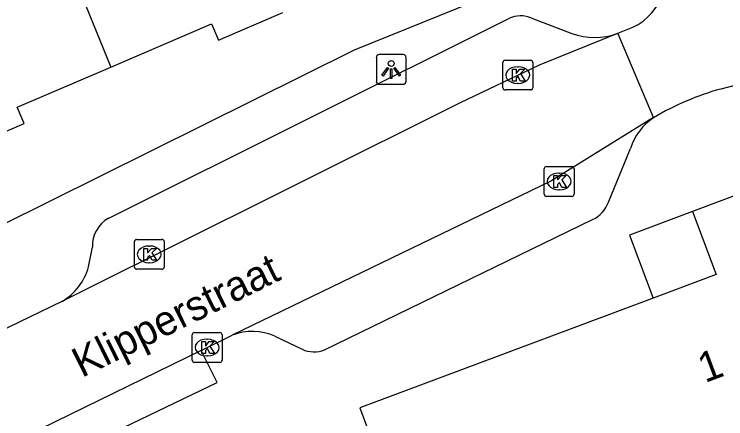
# Model space of a CAD drawing. Extents: x 159377 to 159983, y 382996 to 383595.
# Drawn here: x 159565.6 to 159589.46, y 383433.49 to 383447.05 of the extents above; entities that cross this region are included whole.
import ezdxf

# ---------------------------------------------------------------- set-up
doc = ezdxf.new("R2010")
doc.units = 0
for name, color, linetype in [('IMGEO_Kolk', 7, 'Continuous'), ('IMGEO_Lichtpunt', 7, 'Continuous'), ('IMGEO_Openbare_ruimte_label', 7, 'Continuous'), ('IMGEO_Pand', 7, 'Continuous'), ('IMGEO_Pand_nummerreeks', 7, 'Continuous'), ('IMGEO_Rijbaan_lokaal_gesloten', 7, 'Continuous'), ('IMGEO_Rijbaan_lokaal_open', 7, 'Continuous'), ('IMGEO_Voetpad_open', 7, 'Continuous')]:
    doc.layers.add(name, color=color, linetype=linetype)

msp = doc.modelspace()

# ---------------------------------------------------------------- linework, layer by layer
at = {"layer": 'IMGEO_Kolk'}
for p, q in [((159582.061, 383445.512), (159582.913, 383445.512)), ((159581.986, 383444.586), (159581.986, 383445.438)), ((159582.474, 383445.292), (159582.499, 383445.292)), ((159582.987, 383445.438), (159582.987, 383444.586)), ((159582.497, 383444.732), (159582.472, 383444.732)), ((159582.913, 383444.512), (159582.061, 383444.512)), ((159583.374, 383441.02), (159583.374, 383441.872)), ((159583.449, 383441.946), (159584.301, 383441.946)), ((159584.375, 383441.872), (159584.375, 383441.02)), ((159583.862, 383441.726), (159583.887, 383441.726)), ((159583.885, 383441.166), (159583.86, 383441.166)), ((159584.301, 383440.946), (159583.449, 383440.946)), ((159569.706, 383439.501), (159570.558, 383439.501)), ((159569.631, 383438.575), (159569.631, 383439.427)), ((159570.119, 383439.281), (159570.144, 383439.281)), ((159570.632, 383439.427), (159570.632, 383438.575)), ((159570.142, 383438.721), (159570.117, 383438.721)), ((159570.558, 383438.501), (159569.706, 383438.501)), ((159571.646, 383436.377), (159572.498, 383436.377)), ((159571.571, 383435.451), (159571.571, 383436.303)), ((159572.059, 383436.157), (159572.084, 383436.157)), ((159572.572, 383436.303), (159572.572, 383435.451)), ((159572.082, 383435.597), (159572.057, 383435.597)), ((159572.498, 383435.377), (159571.646, 383435.377))]:
    msp.add_line(p, q, dxfattribs=at)
for points in [[(159582.061, 383445.512), (159582.913, 383445.512)], [(159581.986, 383444.586), (159581.986, 383445.438)], [(159582.307, 383445.212), (159582.43, 383445.212), (159582.43, 383445.061), (159582.56, 383445.212), (159582.724, 383445.212), (159582.578, 383445.061), (159582.731, 383444.812), (159582.579, 383444.812), (159582.494, 383444.976), (159582.43, 383444.909), (159582.43, 383444.812), (159582.307, 383444.812), (159582.307, 383445.212)], [(159582.987, 383445.438), (159582.987, 383444.586)], [(159582.913, 383444.512), (159582.061, 383444.512)], [(159583.374, 383441.02), (159583.374, 383441.872)], [(159583.449, 383441.946), (159584.301, 383441.946)], [(159584.375, 383441.872), (159584.375, 383441.02)], [(159583.695, 383441.646), (159583.818, 383441.646), (159583.818, 383441.495), (159583.948, 383441.646), (159584.112, 383441.646), (159583.966, 383441.495), (159584.119, 383441.246), (159583.967, 383441.246), (159583.882, 383441.41), (159583.818, 383441.343), (159583.818, 383441.246), (159583.695, 383441.246), (159583.695, 383441.646)], [(159584.301, 383440.946), (159583.449, 383440.946)], [(159569.706, 383439.501), (159570.558, 383439.501)], [(159569.631, 383438.575), (159569.631, 383439.427)], [(159570.632, 383439.427), (159570.632, 383438.575)], [(159569.952, 383439.201), (159570.075, 383439.201), (159570.075, 383439.05), (159570.205, 383439.201), (159570.369, 383439.201), (159570.223, 383439.05), (159570.376, 383438.801), (159570.224, 383438.801), (159570.139, 383438.965), (159570.075, 383438.898), (159570.075, 383438.801), (159569.952, 383438.801), (159569.952, 383439.201)], [(159570.558, 383438.501), (159569.706, 383438.501)], [(159571.646, 383436.377), (159572.498, 383436.377)], [(159571.571, 383435.451), (159571.571, 383436.303)], [(159572.572, 383436.303), (159572.572, 383435.451)], [(159571.892, 383436.077), (159572.015, 383436.077), (159572.015, 383435.926), (159572.145, 383436.077), (159572.309, 383436.077), (159572.163, 383435.926), (159572.316, 383435.677), (159572.164, 383435.677), (159572.079, 383435.841), (159572.015, 383435.774), (159572.015, 383435.677), (159571.892, 383435.677), (159571.892, 383436.077)], [(159572.498, 383435.377), (159571.646, 383435.377)]]:
    msp.add_lwpolyline(points, dxfattribs=at)
for centre, start, end in [((159582.063, 383445.436), 91.552, 178.448), ((159582.063, 383445.436), 91.552, 178.448), ((159582.911, 383445.436), 1.552, 88.448), ((159582.911, 383445.436), 1.552, 88.448), ((159582.063, 383444.588), 181.552, 268.448), ((159582.063, 383444.588), 181.552, 268.448), ((159582.911, 383444.588), 271.552, 358.448), ((159582.911, 383444.588), 271.552, 358.448), ((159583.451, 383441.87), 91.552, 178.448), ((159583.451, 383441.87), 91.552, 178.448), ((159584.299, 383441.87), 1.552, 88.448), ((159584.299, 383441.87), 1.552, 88.448), ((159583.451, 383441.022), 181.552, 268.448), ((159583.451, 383441.022), 181.552, 268.448), ((159584.299, 383441.022), 271.552, 358.448), ((159584.299, 383441.022), 271.552, 358.448), ((159569.708, 383439.425), 91.552, 178.448), ((159569.708, 383439.425), 91.552, 178.448), ((159570.556, 383439.425), 1.552, 88.448), ((159570.556, 383439.425), 1.552, 88.448), ((159569.708, 383438.577), 181.552, 268.448), ((159569.708, 383438.577), 181.552, 268.448), ((159570.556, 383438.577), 271.552, 358.448), ((159570.556, 383438.577), 271.552, 358.448), ((159571.648, 383436.301), 91.552, 178.448), ((159571.648, 383436.301), 91.552, 178.448), ((159572.496, 383436.301), 1.552, 88.448), ((159572.496, 383436.301), 1.552, 88.448), ((159571.648, 383435.453), 181.552, 268.448), ((159571.648, 383435.453), 181.552, 268.448), ((159572.496, 383435.453), 271.552, 358.448), ((159572.496, 383435.453), 271.552, 358.448)]:
    msp.add_arc(centre, 0.0765, start, end, dxfattribs=at)
for centre, major_axis, ratio, start_param, end_param in [((159582.473, 383445.012), (-0.387, 0.002), 0.722429, 4.712389, 7.853982), ((159582.498, 383445.012), (-0.39, 0.002), 0.717154, 1.570796, 4.712389), ((159583.861, 383441.446), (-0.387, 0.002), 0.722429, 4.712389, 7.853982), ((159583.886, 383441.446), (-0.39, 0.002), 0.717154, 1.570796, 4.712389), ((159570.118, 383439.001), (-0.387, 0.002), 0.722429, 4.712389, 7.853982), ((159570.143, 383439.001), (-0.39, 0.002), 0.717154, 1.570796, 4.712389), ((159572.058, 383435.877), (-0.387, 0.002), 0.722429, 4.712389, 7.853982), ((159572.083, 383435.877), (-0.39, 0.002), 0.717154, 1.570796, 4.712389)]:
    msp.add_ellipse(centre, major_axis=major_axis, ratio=ratio, start_param=start_param, end_param=end_param, dxfattribs=at)
at = {"layer": 'IMGEO_Lichtpunt'}
for p, q in [((159578.647, 383445.699), (159577.839, 383445.699)), ((159578.647, 383445.699), (159577.839, 383445.699)), ((159577.745, 383445.604), (159577.745, 383444.797)), ((159577.745, 383445.604), (159577.745, 383444.797)), ((159578.741, 383444.797), (159578.741, 383445.604)), ((159578.741, 383444.797), (159578.741, 383445.604)), ((159577.839, 383444.703), (159578.647, 383444.703)), ((159577.839, 383444.703), (159578.647, 383444.703))]:
    msp.add_line(p, q, dxfattribs=at)
for points in [[(159578.119, 383445.268), (159578.158, 383445.24), (159577.97, 383444.978), (159577.932, 383445.005), (159578.119, 383445.268)], [(159578.221, 383445.22), (159578.268, 383445.22), (159578.268, 383444.898), (159578.221, 383444.898), (159578.221, 383445.22)], [(159578.331, 383445.24), (159578.369, 383445.267), (159578.556, 383445.005), (159578.517, 383444.977), (159578.331, 383445.24)]]:
    msp.add_lwpolyline(points, dxfattribs=at)
msp.add_circle((159578.244, 383445.402), 0.0994, dxfattribs=at)
for centre, start, end in [((159577.839, 383445.604), 90, 180), ((159577.839, 383445.604), 90, 180), ((159578.647, 383445.604), 0, 90), ((159578.647, 383445.604), 0, 90), ((159577.839, 383444.797), 180, 270), ((159577.839, 383444.797), 180, 270), ((159578.647, 383444.797), 270, 0), ((159578.647, 383444.797), 270, 360)]:
    msp.add_arc(centre, 0.0946, start, end, dxfattribs=at)
at = {"layer": 'IMGEO_Pand'}
for points in [[(159565.685, 383453.038), (159565.995, 383452.288), (159568.842, 383445.282)], [(159568.842, 383445.282), (159572.22, 383446.728), (159572.458, 383446.177), (159574.615, 383447.107)], [(159563.546, 383442.36), (159565.939, 383443.388), (159565.703, 383443.939), (159568.842, 383445.282)], [(159599.274, 383439.635), (159598.465, 383441.825), (159594.504, 383440.339), (159593.71, 383442.455), (159588.349, 383440.443)], [(159588.349, 383440.443), (159589.143, 383438.327), (159587.027, 383437.535)], [(159587.027, 383437.535), (159577.192, 383433.853), (159577.449, 383433.158)]]:
    msp.add_lwpolyline(points, dxfattribs=at)
at = {"layer": 'IMGEO_Rijbaan_lokaal_gesloten'}
for points in [[(159585.841, 383446.414), (159586.345, 383446.613)], [(159587.043, 383443.584), (159585.841, 383446.414)], [(159593.16, 383445.575), (159591.222, 383445.047), (159589.291, 383444.545)]]:
    msp.add_lwpolyline(points, dxfattribs=at)
for centre, radius, start, end in [((159585.479, 383448.415), 1.999, 295.6804, 25.3019), ((159591.773, 383435.629), 9.255, 105.5565, 120.736)]:
    msp.add_arc(centre, radius, start, end, dxfattribs=at)
at = {"layer": 'IMGEO_Rijbaan_lokaal_open'}
for points in [[(159567.213, 383437.426), (159568.957, 383438.298), (159570.258, 383438.949), (159580.541, 383444.083), (159583.217, 383445.36), (159585.841, 383446.414)], [(159587.043, 383443.584), (159583.598, 383441.454), (159572.913, 383436.291)], [(159562.863, 383435.325), (159567.213, 383437.426)], [(159571.877, 383435.781), (159572.913, 383436.291)], [(159571.877, 383435.781), (159566.472, 383433.144)]]:
    msp.add_lwpolyline(points, dxfattribs=at)
at = {"layer": 'IMGEO_Voetpad_open'}
for points in [[(159581.01, 383447.469), (159577.002, 383445.842), (159561.715, 383438.256), (159560.555, 383437.614), (159559.314, 383437.157)], [(159568.771, 383440.214), (159582.188, 383446.908)], [(159582.954, 383446.918), (159584.297, 383446.407)], [(159585.524, 383440.751), (159586.263, 383442.552)], [(159588.349, 383440.443), (159586.231, 383439.643), (159587.027, 383437.535)], [(159576.012, 383435.798), (159584.998, 383440.168)], [(159568.094, 383438.584), (159568.227, 383439.241)], [(159574.346, 383436.263), (159575.257, 383435.818)], [(159566.472, 383433.144), (159566.987, 383432.102), (159572.41, 383434.706), (159571.877, 383435.781)]]:
    msp.add_lwpolyline(points, dxfattribs=at)
for centre, radius, start, end in [((159582.582, 383446.082), 0.915, 66.0077, 115.4882), ((159585.059, 383448.542), 2.267, 250.3494, 290.1701), ((159588.138, 383441.946), 1.97, 123.7515, 162.0835), ((159584.579, 383441.075), 0.999, 294.7994, 341.0851), ((159569.274, 383439.294), 1.048, 118.6612, 182.9201), ((159566.207, 383439.105), 1.958, 300.9201, 344.5525), ((159573.595, 383434.513), 1.904, 66.7694, 110.9918), ((159575.658, 383436.695), 0.964, 245.4217, 291.5435)]:
    msp.add_arc(centre, radius, start, end, dxfattribs=at)

# ---------------------------------------------------------------- texts
at = {"layer": 'IMGEO_Openbare_ruimte_label'}
msp.add_text('Klipperstraat', height=1, rotation=26.2833, dxfattribs=at).set_placement((159567.87, 383434.851))
at = {"layer": 'IMGEO_Pand_nummerreeks'}
msp.add_text('1', height=1, rotation=20.5233, dxfattribs=at).set_placement((159588.763, 383434.683))

doc.saveas('drawing.dxf')
